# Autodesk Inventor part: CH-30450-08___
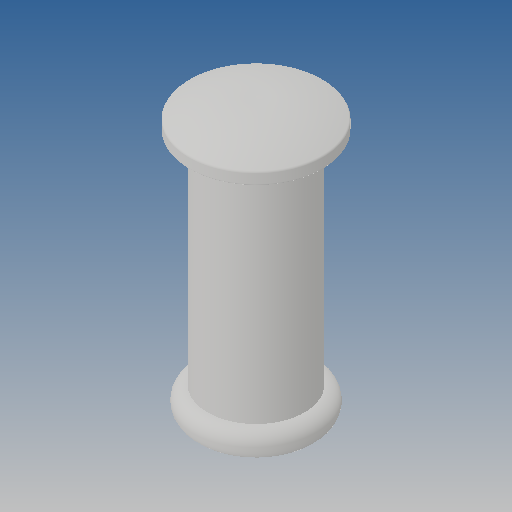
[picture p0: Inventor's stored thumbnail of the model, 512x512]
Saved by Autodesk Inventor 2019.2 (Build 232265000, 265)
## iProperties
Created: 2010-06
Part Number: CH-30450-08___
Material: Ogólny
Document SubType Name: Modeling
Designer: CADENGINEERING4
Density: 1 g/cm^3
Appearance: Domyślna
Author: CADENGINEERING4
Revision Number: ANY
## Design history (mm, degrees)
feature "NONE"
node "Bryła1"
